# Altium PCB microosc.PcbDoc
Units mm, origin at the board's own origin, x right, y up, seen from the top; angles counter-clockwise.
Board outline 134 x 40 mm, 2 copper layers (Top Layer, Bottom Layer); 144 components, 144 nets, 580 pads, 43 vias.
Unrouted connection lines stored in the file: 8.
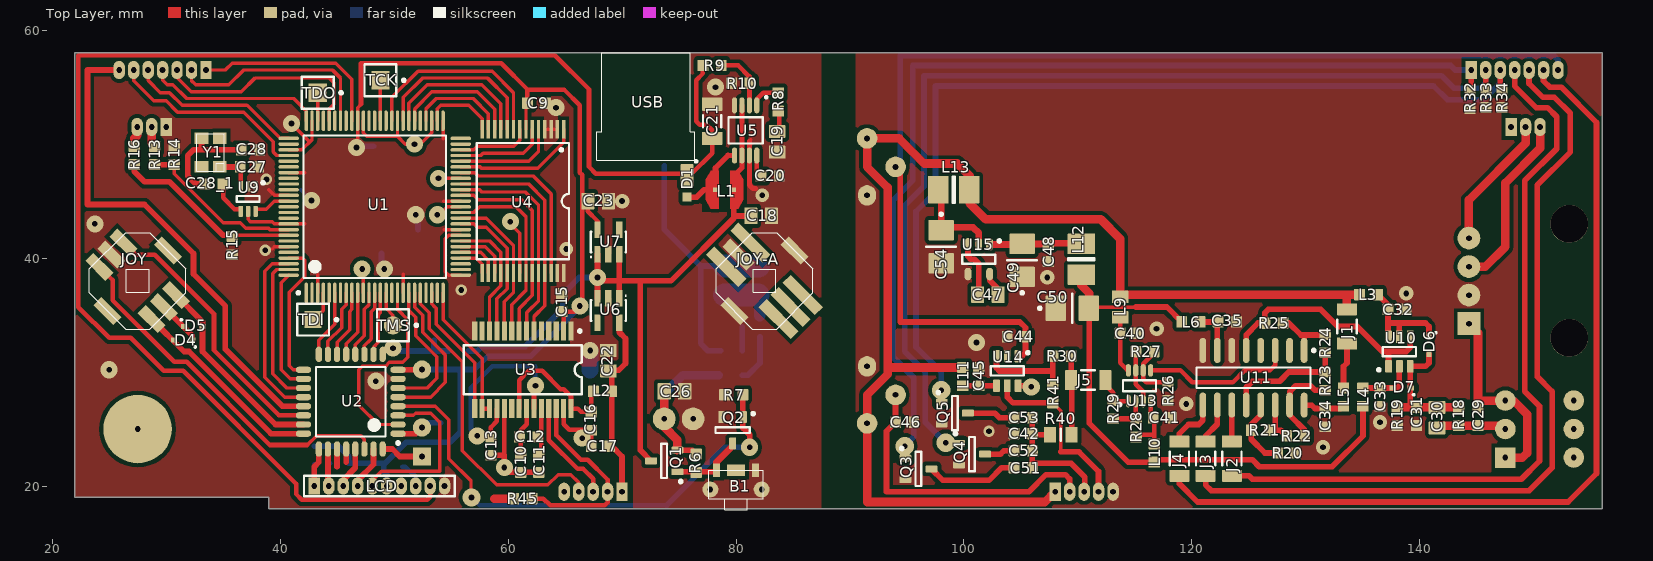
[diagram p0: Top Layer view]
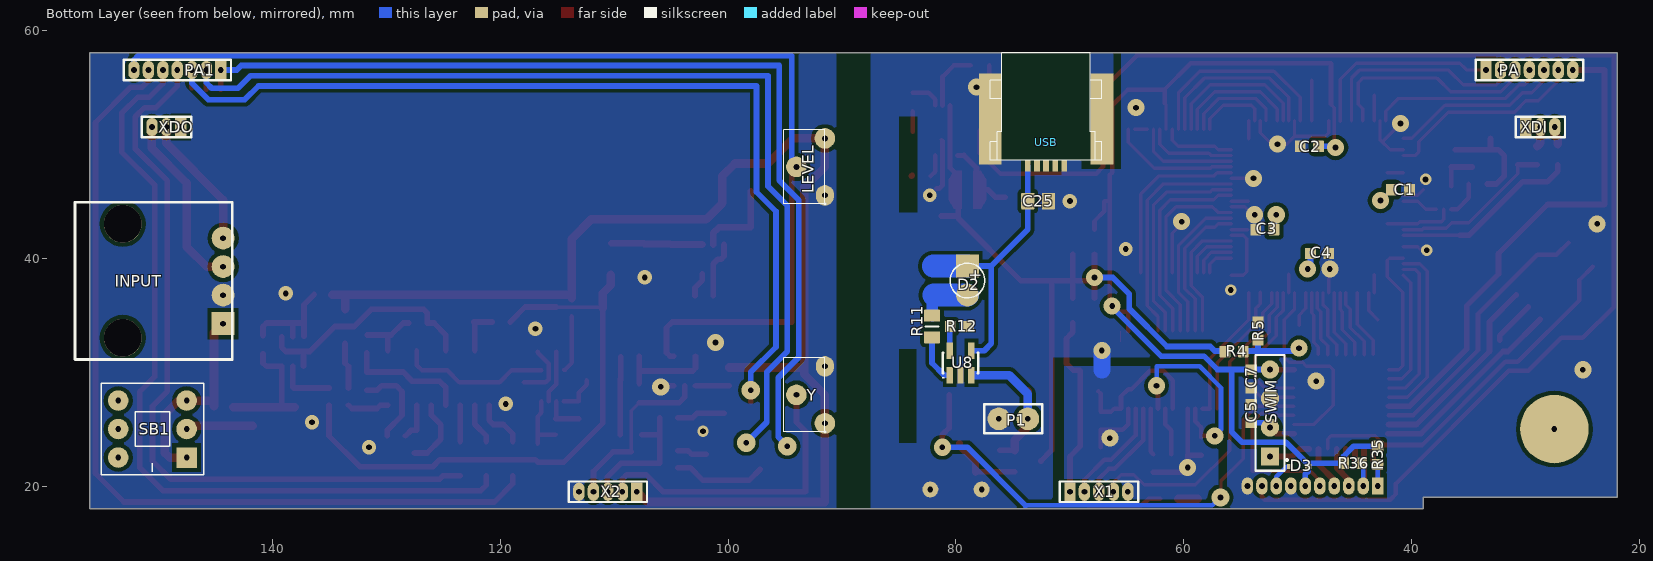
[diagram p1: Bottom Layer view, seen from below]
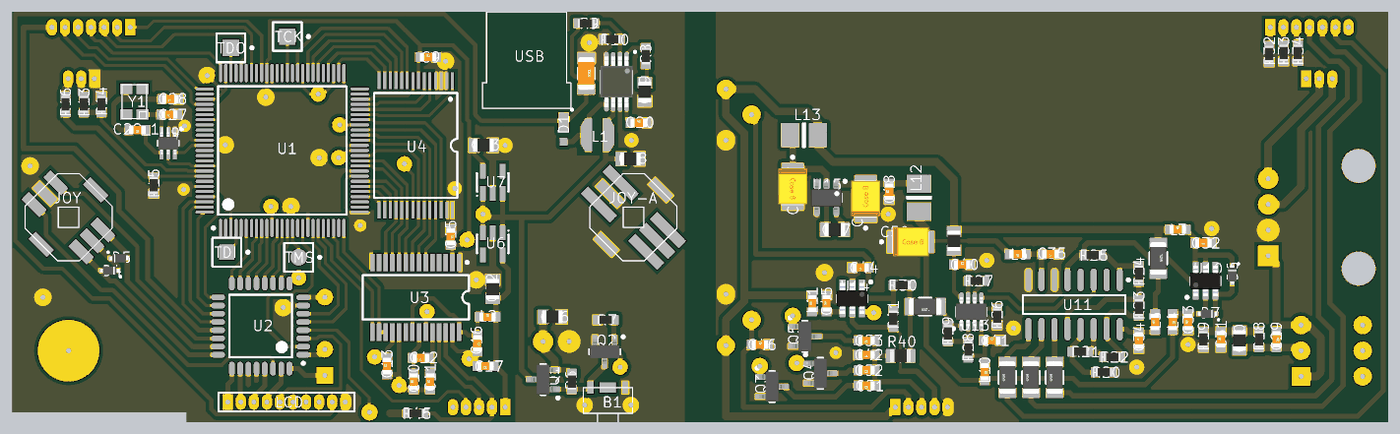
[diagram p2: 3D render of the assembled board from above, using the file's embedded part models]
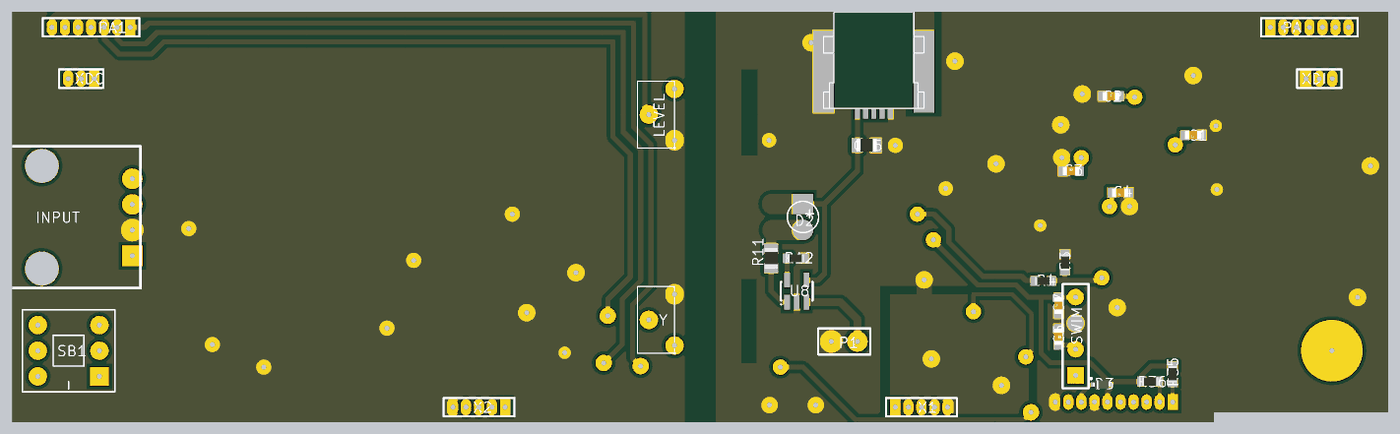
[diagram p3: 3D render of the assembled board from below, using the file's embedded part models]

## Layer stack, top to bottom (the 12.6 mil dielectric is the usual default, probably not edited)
Top Layer: signal copper 0.0356
Dielectric: dielectric 0.32, FR-4, Dk 4.8
Bottom Layer: signal copper 0.0356

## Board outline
22,19 39,19 39,18 156,18 156,58 22,58

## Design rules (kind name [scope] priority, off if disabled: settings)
Clearance Clearance_1 [IsPad Or IsTrack vs IsPad Or IsTrack] p1: gap=0.2
Clearance [All] p2: gap=0.35
ComponentClearance [All] p1 off: gap=0.254 collisioncheckmode=3 verticalgap=0.254 showdistances=FALSE
FanoutControl Fanout_BGA [IsBGA] p1 off: bgadir=Out bgaviamode=Centered fanoutstyle=Auto fanoutdirection=Alternating viagrid=0.025 // Fanout_BGA (Default Rule)
FanoutControl Fanout_LCC [IsLCC] p2 off: bgadir=Out bgaviamode=Centered fanoutstyle=Auto fanoutdirection=Alternating viagrid=0.025 // Fanout_LCC (Default Rule)
FanoutControl Fanout_SOIC [IsSOIC] p3 off: bgadir=Out bgaviamode=Centered fanoutstyle=Auto fanoutdirection=Alternating viagrid=0.025 // Fanout_SOIC (Default Rule)
FanoutControl Fanout_Small [(CompPinCount < 5)] p4 off: bgadir=Out bgaviamode=Centered fanoutstyle=Auto fanoutdirection=OutThenIn viagrid=0.025 // Fanout_Small (Default Rule)
FanoutControl Fanout_Default [All] p5 off: bgadir=Out bgaviamode=Centered fanoutstyle=Auto fanoutdirection=Alternating viagrid=0.025 // Fanout_Default (Default Rule)
HoleSize [All] p1 off: absolutevalues=TRUE maxlimit=2.54 minlimit=0.025 maxpercent=80.000 minpercent=20.000
HoleToHoleClearance [All] p1 off: gap=0.254 allowstackedmicrovias=TRUE
LayerPairs [All] p1 off: enforce=TRUE
MinimumSolderMaskSliver [All] p1 off: minsoldermaskwidth=0.254
NetAntennae [All] p1 off: netantennaetolerance=0
PlaneConnect [All] p1: planeconnectstyle=Relief reliefexpansion=0.508 reliefentries=4 reliefconductorwidth=0.5 reliefairgap=-0.1
PolygonConnect [All] p1: connectstyle=Relief reliefconductorwidth=0.5 reliefentries=4 polygonreliefangle="90 Angle" airgapwidth=-0.1
RoomDefinition analog [InComponentClass('analog')] p1: confinementstyle=ConfineOut formatcopy=TRUE lockcomponents=FALSE outline 101.6,60.5 92.6,60.5 92.6,58.5 101.6,58.5
RoomDefinition dig [InComponentClass('dig')] p2: confinementstyle=ConfineOut formatcopy=TRUE lockcomponents=FALSE outline 22.9,58.4 30.8,58.4 30.8,60.6 22.9,60.6
RoutingVias [All] p1: holewidth=0.5 width=1.6 viastyle="Through Hole" minholewidth=0.5 minwidth=1 maxholewidth=0.5 maxwidth=1.6
SilkToSilkClearance [All] p1 off: silktosilkclearance=0.254
SilkscreenOverComponentPads [IsPad] p1 off: minsilkscreentomaskgap=0.254
SolderMaskExpansion [All] p1 off: expansion=0.102
Width [All] p1 off: maxlimit=2 minlimit=0.2 preferedwidth=0.3
14 further rules are at their usual default settings.

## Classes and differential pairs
component class analog: C29 C30 C31 C32 C33 C34 C35 C40 C41 C42 C44 C45 C46 C47 C48 C49 C50 C51 C52 C53 C54 D6 D7 INPUT J1 J2 J3 J4 J5 L3 L4 L5 L6 L9 L10 L11 L12 L13 LEVEL PA1 Q3 Q4 Q5 R18 R19 R20 R21 R22 R23 R24 R25 R26 R27 R28 R29 R30 R32 R33 R34 R40 R41 SB1 U10 U11 U13 U14 U15 X2 XDO Y
component class dig: B1 C1 C2 C3 C4 C5 C7 C9 C10 C11 C12 C13 C15 C16 C17 C18 C19 C20 C21 C22 C23 C25 C26 C27 C28 C28_1 D1 D2 D3 D4 D5 JOY JOY-A L1 L2 LCD P1 PA Q1 Q2 R4 R5 R6 R7 R8 R9 R10 R11 R12 R13 R14 R15 R16 R35 R36 R45 SWIM TCK TDI TDO TMS U1 U2 U3 U4 U5 U6 U7 U8 U9 USB X1 XDI Y1

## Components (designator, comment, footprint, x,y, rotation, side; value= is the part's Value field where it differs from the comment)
B1 "Micro Button" "Micro Button" 80,21.4 r180 top
C1 "Cap" C0603NH080 41,46 r0 bottom
C2 "Cap" C0603NH080 49,49.8 r180 bottom
C3 "Cap" C0603NH080 52.9,42.5 r180 bottom
C4 "Cap" C0603NH080 48.1,40.4 r0 bottom
C5 "Cap" C0603NH080 54.1,26.35 r270 bottom
C7 "Cap" C0603NH080 54.1,29.4 r90 bottom
C9 "Cap" C0603NH080 62.5,53.6 r0 top
C10 "Cap" C0603NH080 61.1,22 r90 top
C11 "Cap" C0603NH080 62.7,22 r90 top
C12 "Cap" C0603NH080 61.8,24.3 r180 top
C13 "Cap" C0603NH080 58.5,23.5 r90 top
C15 "Cap" C0603NH080 64.7,36.1 r270 top
C16 "Cap" C0603NH080 67.3,25.7 r270 top
C17 "Cap" C0603NH080 68.1,23.5 r180 top
C18 "Cap" C0805NH145#1 82.2,43.7 r180 top
C19 "Cap" C0805NH145#1 83.6,50.2 r90 top
C20 "Cap" C0603NH080 83,47.2 r0 top
C21 "Cap" C1206NH190 77.9,52 r270 top
C22 "Cap" C0805NH145#1 68.8,31 r270 top
C23 "Cap" C0805NH145#1 67.9,45 r180 top
C25 "Cap" C0805NH145#1 72.8,45 r180 bottom
C26 "Cap" C0805NH145#1 74.6,28.3 r180 top
C27 "Cap" C0603NH080 37.3,48 r180 top
C28 "Cap" C0603NH080 37.4,49.5 r180 top
C28_1 "Cap" C0603NH080 34.2,46.5 r180 top
C29 "Cap" C0603NH080 145.1,26.1 r270 top
C30 "Cap" C0805NH145#1 141.5,26 r270 top
C31 "Cap" C0603NH080 139.7,26.1 r90 top
C32 "Cap" C0603NH080 138,35.5 r180 top
C33 "Cap" C0603NH080 136.5,27.8 r90 top
C34 "Cap" C0603NH080 131.7,26 r90 top
C35 "Cap" C0603NH080 123.1,34.4 r180 top
C40 "Cap" C0603NH080 114.5,33.4 r0 top
C41 "Cap" C0603NH080 117.4,26 r0 top
C42 "Cap" C0603NH080 105.2,24.6 r180 top
C44 "Cap" C0603NH080 104.6,33.1 r180 top
C45 "Cap" C0603NH080 101.3,29.6 r90 top
C46 "Cap" C0603NH080 94.8,25.6 r0 top
C47 "Cap" C0805NH145#1 102.1,36.8 r0 top
C48 "Cap" C0603NH080 107.4,40.5 r90 top
C49 "ECap" CAPMP3528X210N_KEMET 105.1,39.8 r90 top
C50 "ECap" CAPMP3528X210N_KEMET 109.5,35.6 r0 top
C51 "Cap" C0603NH080 105.2,21.6 r180 top
C52 "Cap" C0603NH080 105.2,23.1 r180 top
C53 "Cap" C0603NH080 105.2,26 r180 top
C54 "ECap" CAPMP3528X210N_KEMET 98,41 r270 top
D1 "D_Schottky" SOD323FL_VISHAY_MICROSMP 75.7,46.6 r270 top
D2 "Green" SvetoDiod-D3 79,39.3 r270 bottom
D3 "Diode" SOD523 49.9,21.7 r180 bottom
D4 "Diode" SOD523 31.5,32.8 r180 top
D5 "Diode" SOD523 32.4,34 r0 top
D6 "Diode" SOD523 140.8,32.4 r270 top
D7 "Diode" SOD523 138.4,28.6 r180 top
INPUT "4pin" 4pin_2.5_Audio 144.3,38 r90 bottom
J1 "R" R1206NH084 133.6,34 r270 top
J2 "R" R1206NH084 123.5,22.4 r90 top
J3 "R" R1206NH084 121.2,22.4 r90 top
J4 "R" R1206NH084 118.9,22.4 r90 top
J5 "R" R1206NH084 110.9,29.3 r180 top
JOY "Joystick" Joystick#1 27.5,38 r270 top
JOY-A "Joystick" Joystick#2 82.5,38 r270 top
L1 "L" L1212_muR_LQH3NP 79,46 r180 top
L2 "BEAD" C0603NH080 68.3,28.3 r0 top
L3 "BEAD" C0603NH080 135.5,36.8 r0 top
L4 "BEAD" C0603NH080 135,27.8 r270 top
L5 "BEAD" C0603NH080 133.3,27.8 r90 top
L6 "BEAD" C0603NH080 119.9,34.4 r180 top
L9 "BEAD" C0805NH145#2 113.7,35.7 r90 top
L10 "BEAD" C0603NH080 116.7,22.9 r270 top
L11 "BEAD" C0603NH080 99.9,29.6 r90 top
L12 "L" L1210_muR_LQH32 110.3,39.9 r270 top
L13 "L" L1210_muR_LQH32 99.1,46 r0 top
LCD "MHDR1X10" MHDR1X10 43,20 r0 top
LEVEL "Res_Var" CA6H#1 91.5,48 r90 bottom
P1 "Header 2" HDR1X2 73.7,25.9 r0 bottom
PA "MHDR1X7" MHDR1X7 33.5,56.5 r180 bottom
PA1 "MHDR1X7" MHDR1X7 144.5,56.5 r0 bottom
Q1 "IRLML2244" SOT23-3_DISCRETE 73.7,22.2 r180 top
Q2 "IRLML2402" SOT23-3_DISCRETE 79.7,24.9 r270 top
Q3 "IRLML2402" SOT23-3_DISCRETE 96,21.5 r0 top
Q4 "IRLML2402" SOT23-3_DISCRETE 100.7,22.8 r0 top
Q5 "IRLML2402" SOT23-3_DISCRETE 99.2,26.4 r0 top
R4 "R" R0603N 55.6,31.8 r0 bottom
R5 "R" R0603N 53.5,33.6 r270 bottom
R6 "R" R0603N 76.5,22 r270 top
R7 "R" R0603N 79.8,28 r0 top
R8 "R" R0603N 83.7,53.7 r90 top
R9 "R" R0603N 77.9,56.9 r180 top
R10 "R" R0603N 80.4,55.35 r0 top
R11 "R" R0805NH070 82.1,34 r270 bottom
R12 "R" R0603N 79.7,34 r0 bottom
R13 "R" R0603N 29,49 r90 top
R14 "R" R0603N 30.7,49 r90 top
R15 "R" R0603N 35.8,41.1 r270 top
R16 "R" R0603N 27.2,49 r90 top
R18 "R" R0603N 143.4,26.1 r270 top
R19 "R" R0603N 138,26.1 r90 top
R20 "R" R0603N 128.3,22.9 r180 top
R21 "R" R0603N 126,24.9 r0 top
R22 "R" R0603N 129.1,24.4 r0 top
R23 "R" R0603N 131.7,29.2 r90 top
R24 "R" R0603N 131.7,32.5 r90 top
R25 "R" R0603N 127.2,34.3 r180 top
R26 "R" R0603N 117.9,28.3 r270 top
R27 "R" R0603N 115.9,31.8 r180 top
R28 "R" R0603N 115.1,25.1 r270 top
R29 "R" R0603N 113.1,26.7 r90 top
R30 "R" R0603N 108.6,31.4 r180 top
R32 "R" R0603N 144.4,53.9 r270 top
R33 "R" R0603N 145.8,54 r270 top
R34 "R" R0603N 147.2,54 r270 top
R35 "R" R0603N 43,22.7 r90 bottom
R36 "R" R0603N 45.2,22 r0 bottom
R40 "R" R0805NH070 108.5,24.5 r180 top
R41 "R" R0603N 107.8,28.1 r270 top
R45 "R" R0603N 61.3,18.9 r180 top
SB1 "SB_8x8" SB_8x8 150.5,25 r90 bottom
SWIM "Header 4" HDR1X4 52.45,22.6 r90 bottom
TCK "Socket" PIN1#1 48.8,55.6 r270 top
TDI "Socket" PIN1#2 42.9,34.6 r270 top
TDO "Socket" PIN1#1 43.3,54.5 r270 top
TMS "Socket" PIN1#3 49.9,34.1 r270 top
U1 "EPM3064ATC-100" TQFP100_N 48.3,44.5 r90 top
U2 "STM8L151K6T" TQFP32_L 46.2,27.4 r180 top
U3 "AD9203" RS-28 61.3,30.2 r180 top
U4 "AS7C3256A" TSOP28 61.3,45 r180 top
U5 "ADP1612" MSOP8 80.85,51.2 r270 top
U6 "ADP150AU-3.0" RT-5 68.8,35.4 r180 top
U7 "ADP150AU-3.0" RT-5 68.8,41.4 r0 top
U8 "MCP73831T" S5 79.6,30.8 r180 bottom
U9 "74AUP1Z04" SC70-6 37.2,45.2 r270 top
U10 "OPA357AIDBV" SOT23-6RR 138.2,31.8 r90 top
U11 "MC74HC4051AD" 751B-05_N 125.4,29.5 r270 top
U13 "AD8039" TSOT23-8 115.4,28.8 r90 top
U14 "TLV3501AIDBV" SOT23-6RR 103.8,30.1 r270 top
U15 "LM828" SOT23-5 101.3,39.9 r270 top
USB "USB-miniB" USB-B_CrossBoard 72.1,48.1 r0 top locked
X1 "MHDR1X5" MHDR1X5 70,19.5 r180 bottom
X2 "MHDR1X5" MHDR1X5 108,19.5 r0 bottom
XDI "MHDR1X3" MHDR1X3 30,51.5 r180 bottom
XDO "MHDR1X3" MHDR1X3 148,51.5 r0 bottom
Y "Res_Var" CA6H#2 91.5,28 r90 bottom
Y1 "Quarz Rezonator SMD" QUARZ_REC_25x32 34.7,48 r90 top

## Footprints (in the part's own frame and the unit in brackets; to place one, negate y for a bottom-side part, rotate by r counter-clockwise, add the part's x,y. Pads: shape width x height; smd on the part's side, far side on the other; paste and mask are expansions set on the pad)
4pin_2.5_Audio [mm] "Internal Audio connector for cabel"
  rect 2x2 hole 0.5: 1(-3.75,0)
  round 2 hole 0.5: 2(-1.25,0) 3(1.25,0) 4(3.75,0)
  round 3.3 hole 3.3: 5(-5,8.8) 5(5,8.8)
  silkscreen extent -6.9,-0.8 6.9,13
751B-05_N [mm] "SOIC, 16-Leads, Body 9.9x3.9mm, Pitch 1.27mm, IPC Medium Density"
  oval 2.2x0.6 smd: 1(-2.4,4.445) 2(-2.4,3.175) 3(-2.4,1.905) 4(-2.4,0.635) 5(-2.4,-0.635) 6(-2.4,-1.905) 7(-2.4,-3.175) 8(-2.4,-4.445) 9(2.4,-4.445) 10(2.4,-3.175) 11(2.4,-1.905) 12(2.4,-0.635) 13(2.4,0.635) 14(2.4,1.905) 15(2.4,3.175) 16(2.4,4.445)
  silkscreen extent -2.52,-5 0.9,5.42, body extent -1.95,-4.95 1.95,4.95, height 1.75
C0603NH080 [mm] "Capacitor,Chip;1.60mm L X 0.80mm W X 0.90mm H"
  rrect10% 0.95x1 smd paste-0.025 mask+0.05: 1(-0.8,0) 2(0.8,0)
  body extent -0.8,-0.4 0.8,0.4, height 0.3
C0805NH145#1 [mm] "Capacitor,Chip;2.00mm L X 1.25mm W X 1.45mm H"
  rrect10% 1.15x1.45 smd paste-0.025 mask+0.05: 1(-0.9,0) 2(0.9,0)
  body extent -1,-0.62 1,0.63, height 0.6
C0805NH145#2 [mm] "Capacitor,Chip;2.00mm L X 1.25mm W X 1.45mm H"
  rrect10% 1.1x1.45 smd paste-0.025 mask+0.05: 1(-0.9,0) 2(0.9,0)
  body extent -1,-0.62 1,0.63, height 0.6
C1206NH190 [mm] "Capacitor, Chip; 3.20mm L X 1.60mm W X 1.90mm H"
  rrect10% 1.15x1.8 smd paste-0.025 mask+0.05: 1(-1.5,0) 2(1.5,0)
  silkscreen extent -0.55,-0.8 0.55,0.8, body extent -1.6,-0.8 1.6,0.8, height 1
CA6H#1 [mm] "Variable Resistor 6.5x6.5x3.5mm Vertical"
  oval 1.8x1.6 hole 0.5: 1(-2.5,0)
  round 1.8 hole 0.5: 2(2.5,0) 3(0,2.5)
  silkscreen extent -3.25,0 3.25,3.6
CA6H#2 [mm] "Variable Resistor 6.5x6.5x3.5mm Vertical"
  round 1.8 hole 0.5: 1(-2.5,0) 3(0,2.5)
  oval 1.8x1.6 hole 0.5: 2(2.5,0)
  silkscreen extent -3.25,0 3.25,3.6
CAPMP3528X210N_KEMET [mm]
  rrect11% 1.8x2.25 smd paste-0.05 mask+0.05: A(-1.45,0) C(1.45,0)
  silkscreen extent -2.97,-1.3 0,1.3, body extent -1.85,-1.41 1.85,1.41, height 2.09
HDR1X2 [mm] "Connector; Header; 2 Position"
  round 2 hole 0.5: 1(0,0) 2(2.54,0)
  silkscreen extent -1.27,-1.27 3.81,1.27
HDR1X4 [mm] "Connector; Header; 4 Position"
  rect 1.6x1.6 hole 0.5: 1(0,0)
  round 1.6 hole 0.5: 2(2.54,0) 4(7.62,0)
  round 1.6 smd: 3(5.08,0)
  silkscreen extent -1.27,-1.27 8.89,1.27
Joystick#1 [mm] "Joystick Siemens"
  rect 2.5x1 smd rot 45: 1(-3.359,-1.237) 2(-2.298,-2.298) 3(-1.237,-3.359) 4(3.359,1.237) 5(2.298,2.298) 6(1.237,3.359) 7(-2.652,2.652) 8(2.652,-2.652)
  silkscreen extent -4.24,-4.24 4.24,4.24
Joystick#2 [mm] "Joystick Siemens"
  rect 4x1 smd rot 45: 1(-3.359,-1.237) 3(-1.237,-3.359) 4(3.359,1.237) 5(2.298,2.298) 6(1.237,3.359)
  rect 3x1 smd rot 45: 2(-2.298,-2.298)
  rect 2.5x1 smd rot 45: 7(-2.652,2.652) 8(2.652,-2.652)
  silkscreen extent -4.24,-4.24 4.24,4.24
L1210_muR_LQH32 [mm]
  rrect5% 1.8x2.4 smd paste-0.025 mask+0.05: 1(-1.35,0) 2(1.35,0)
  silkscreen extent -0.1,-1.15 0.1,1.15
L1212_muR_LQH3NP [mm]
  rect 0.4x0.4 smd paste-0.4 mask-0.4: 1(-0.8,0) 2(0.8,0)
  Top Layer region: 0.5,1.65 1.2,1.65 1.65,0.9 1.65,-0.9 1.343,-1.411 1.2,-1.65 0.5,-1.65
  Top Layer region: -0.5,1.65 -1.2,1.65 -1.65,0.9 -1.65,-0.9 -1.341,-1.415 -1.2,-1.65 -0.5,-1.65
  body extent -1.49,-1.5 1.5,1.5, height 1.5
MHDR1X3 [mm] "Connector; Header; 3 Position"
  rect 1x1.6 hole 0.5: 1(0,0)
  oval 1x1.6 hole 0.5: 2(1.27,0) 3(2.54,0)
  silkscreen extent -0.9,-0.9 3.44,0.9
MHDR1X5 [mm] "Connector; Header; 5 Position"
  rect 1x1.6 hole 0.5: 1(0,0)
  oval 1x1.6 hole 0.5: 2(1.27,0) 3(2.54,0) 4(3.81,0) 5(5.08,0)
  silkscreen extent -0.9,-0.9 5.98,0.9
MHDR1X7 [mm] "Connector; Header; 7 Position"
  rect 1x1.6 hole 0.5: 1(0,0)
  oval 1x1.6 hole 0.5: 2(1.27,0) 3(2.54,0) 4(3.81,0) 5(5.08,0) 6(6.35,0) 7(7.62,0)
  silkscreen extent -0.9,-0.9 8.52,0.9
MHDR1X10 [mm] "Connector; Header; 10 Position"
  rect 1x1.5 hole 0.5: 1(0,0)
  oval 1x1.5 hole 0.5: 2(1.27,0) 3(2.54,0) 4(3.81,0) 5(5.08,0) 6(6.35,0) 7(7.62,0) 8(8.89,0) 9(10.16,0) 10(11.43,0)
  silkscreen extent -0.9,-0.9 12.33,0.9
"Micro Button" [mm]
  rect 0.6x1.2 smd: 1(-1.7,0) 2(1.7,0)
  round 1.4 hole 0.5: 3(-2.25,1.7) 3(2.25,1.7)
  rect 1.6x1 smd: 4(0,0)
  silkscreen extent -2.4,0 2.4,3.5
MSOP8 [mm] "SOP,0.65mm pitch;8 pin,3.00mm W X 3.00mm L X 1.09mm H body"
  oval 1.4x0.45 smd mask+0.05: 1(-2.2,0.975) 2(-2.2,0.325) 3(-2.2,-0.325) 4(-2.2,-0.975) 5(2.2,-0.975) 6(2.2,-0.325) 7(2.2,0.325) 8(2.2,0.975)
  silkscreen extent -3,-1.5 1.15,1.9, body extent -2.47,-1.55 2.47,1.55, height 1.1
PIN1#1 [mm] "Connector; Plug"
  rect 1.6x1.6 smd: 1(0,0)
  silkscreen extent -1.4,-1.4 1.4,2.18
PIN1#2 [mm] "Connector; Plug"
  rect 1.5x1.5 smd: 1(0,0)
  silkscreen extent -1.4,-1.4 1.4,2.18
PIN1#3 [mm] "Connector; Plug"
  round 1.6 smd: 1(0,0)
  silkscreen extent -1.4,-1.4 1.4,2.18
QUARZ_REC_25x32 [mm] "Quarz rezonatro or generator 2.5x3.2mm"
  rect 1x1.2 smd: 1(0,0) 2(2.5,0) 3(2.5,1.6) 4(0,1.6)
  silkscreen extent -0.4,-0.4 2.9,2
R0603N [mm] "Resistor, Chip, 1.60mm L x 0.80mm W x 0.50mm H"
  rrect10% 0.95x1 smd paste-0.025 mask+0.05: 1(-0.8,0) 2(0.8,0)
  body extent -0.8,-0.4 0.8,0.4, height 0.46
R0805NH070 [mm] "Resistor, Chip, 2.00mm L x 1.25mm W x 0.70mm H"
  rrect10% 1.05x1.4 smd paste-0.025 mask+0.05: 1(-0.95,0) 2(0.95,0)
  silkscreen extent 0,-0.55 0,0.55, body extent -1,-0.62 1,0.63, height 0.41
R1206NH084 [mm] "Resistor, Chip, 3.20mm L x 1.60mm W x 0.84mm H"
  rrect10% 1.05x1.75 smd paste-0.025 mask+0.05: 1(-1.5,0) 2(1.5,0)
  silkscreen extent -0.6,-0.85 0.6,0.85, body extent -1.6,-0.8 1.6,0.8, height 1
RS-28 [mm] "SSOP; 28 Leads; Body Width 5.3 mm; Pitch 0.65 mm"
  rect 0.45x1.7 smd: 1(-4.225,-3.4) 2(-3.575,-3.4) 3(-2.925,-3.4) 4(-2.275,-3.4) 5(-1.625,-3.4) 6(-0.975,-3.4) 7(-0.325,-3.4) 8(0.325,-3.4) 9(0.975,-3.4) 10(1.625,-3.4) 11(2.275,-3.4) 12(2.925,-3.4) 13(3.575,-3.4) 14(4.225,-3.4) 15(4.225,3.4) 16(3.575,3.4) 17(2.925,3.4) 18(2.275,3.4) 19(1.625,3.4) 20(0.975,3.4) 21(0.325,3.4) 22(-0.325,3.4) 23(-0.975,3.4) 24(-1.625,3.4) 25(-2.275,3.4) 26(-2.925,3.4) 27(-3.575,3.4) 28(-4.225,3.4)
  silkscreen extent -5.18,-3.52 5.18,2.15
RT-5 [mm] "SOT-23/SC-74A; 5 Leads; Body 3.1 x 3 mm, inc. leads (LxW max)"
  rect 0.55x1.45 smd: 1(-0.95,-1.075) 2(0,-1.075) 3(0.95,-1.075) 4(0.95,1.075) 5(-0.95,1.075)
  silkscreen extent -1.58,-1.35 1.55,0.9
S5 [mm] "SOT-23/SC-74A; 5 Leads; Body 3.1 x 3 mm, inc. leads (LxW max)"
  rect 0.55x1.45 smd: 1(-0.95,-1.075) 2(0,-1.075) 3(0.95,-1.075) 4(0.95,1.075) 5(-0.95,1.075)
  silkscreen extent -1.58,-1.35 1.55,0.9
SB_8x8 [mm] "Кнопка 8х8мм"
  rect 1.8x1.8 hole 0.5: 1(-2.5,-3)
  round 1.8 hole 0.5: 2(0,-3) 3(2.5,-3) 4(2.5,3) 5(0,3) 6(-2.5,3)
  silkscreen extent -4,-4.5 4,4.5
SC70-6 [mm] "SOT,0.65mm pitch;6 pin,1.35mm W X 2.20mm L X 1.00mm H body"
  rrect40% 0.95x0.4 smd mask+0.05: 1(-1.1,0.65) 2(-1.1,0) 3(-1.1,-0.65) 4(1.1,-0.65) 5(1.1,0) 6(1.1,0.65)
  silkscreen extent -1.53,-1 0.25,1.43, body extent -1.05,-1 1.05,1, height 0.95
SOD323FL_VISHAY_MICROSMP [mm]
  rrect12% 0.8x0.8 smd paste-0.025 mask+0.05: A(1.25,0)
  rrect9% 2x1.1 smd paste-0.05 mask+0.05: C(-0.65,0)
  silkscreen extent -1.98,0.7 -1.78,0.9, body extent -1.15,-0.7 1.15,0.7, height 0.65
SOD523 [mm]
  rrect15% 0.55x0.45 smd paste-0.025 mask+0.05: A(0.8,0) C(-0.8,0)
  silkscreen extent -1.09,0.55 -1.01,0.63, body extent -0.91,-0.42 0.92,0.42, height 0.71
SOT23-3_DISCRETE [mm] "SOT,0.95mm pitch;3 pin,1.40mm W X 3.04mm L X 1.12mm H body"
  rrect25% 1.05x0.6 smd paste-0.025 mask+0.05: 1(-1.15,0.95) 2(-1.15,-0.95) 3(1.15,0)
  silkscreen extent -1.58,-1.5 0.25,1.92, body extent -1.25,-1.46 1.23,1.46, height 1.02
SOT23-5 [mm] "SOT,0.95mm pitch;5 pin,1.70mm W X 3.00mm L X 1.45mm H body"
  oval 1.1x0.6 smd mask+0.05: 1(-1.3,0.95) 2(-1.3,0) 3(-1.3,-0.95) 4(1.3,-0.95) 5(1.3,0.95)
  silkscreen extent -1.72,-1.45 0.4,1.92, body extent -1.5,-1.52 1.5,1.48, height 1.55
SOT23-6RR [mm] "SOT,0.95mm pitch;6 pin,1.70mm W X 3.00mm L X 1.45mm H body"
  rrect25% 1.1x0.6 smd mask+0.05: 1(-1.3,0.95) 2(-1.3,0) 3(-1.3,-0.95) 4(1.3,-0.95) 5(1.3,0) 6(1.3,0.95)
  silkscreen extent -1.72,-1.45 0.4,1.92, body extent -1.5,-1.5 1.5,1.5, height 1.3
SvetoDiod-D3 [mm] "SvetoDiod Diametr=3mm"
  rect 2x2 smd: A(0,0)
  round 2 smd: K(2.54,0)
  silkscreen extent -0.25,-1.52 2.79,1.52
TQFP32_L [mm] "Thin QFP, 32-Leads, Body 7x7mm, Pitch 0.8mm, IPC High Density"
  oval 1.35x0.55 smd: 1(-4.15,2.8) 2(-4.15,2) 3(-4.15,1.2) 4(-4.15,0.4) 5(-4.15,-0.4) 6(-4.15,-1.2) 7(-4.15,-2) 8(-4.15,-2.8) 17(4.15,-2.8) 18(4.15,-2) 19(4.15,-1.2) 20(4.15,-0.4) 21(4.15,0.4) 22(4.15,1.2) 23(4.15,2) 24(4.15,2.8)
  oval 0.55x1.35 smd: 9(-2.8,-4.15) 10(-2,-4.15) 11(-1.2,-4.15) 12(-0.4,-4.15) 13(0.4,-4.15) 14(1.2,-4.15) 15(2,-4.15) 16(2.8,-4.15) 25(2.8,4.15) 26(2,4.15) 27(1.2,4.15) 28(0.4,4.15) 29(-0.4,4.15) 30(-1.2,4.15) 31(-2,4.15) 32(-2.8,4.15)
  silkscreen extent -4.28,-3.05 3.05,3.75, body extent -3.5,-3.5 3.5,3.5, height 1.6
TQFP100_N [mm] "Thin QFP, 100-Leads, Body 14x14mm, Pitch 0.5mm, IPC Medium Density"
  oval 1.8x0.3 smd: 1(-7.55,6) 2(-7.55,5.5) 3(-7.55,5) 4(-7.55,4.5) 5(-7.55,4) 6(-7.55,3.5) 7(-7.55,3) 8(-7.55,2.5) 9(-7.55,2) 10(-7.55,1.5) 11(-7.55,1) 12(-7.55,0.5) 13(-7.55,0) 14(-7.55,-0.5) 15(-7.55,-1) 16(-7.55,-1.5) 17(-7.55,-2) 18(-7.55,-2.5) 19(-7.55,-3) 20(-7.55,-3.5) 21(-7.55,-4) 22(-7.55,-4.5) 23(-7.55,-5) 24(-7.55,-5.5) 25(-7.55,-6) 51(7.55,-6) 52(7.55,-5.5) 53(7.55,-5) 54(7.55,-4.5) 55(7.55,-4) 56(7.55,-3.5) 57(7.55,-3) 58(7.55,-2.5) 59(7.55,-2) 60(7.55,-1.5) 61(7.55,-1) 62(7.55,-0.5) 63(7.55,0) 64(7.55,0.5) 65(7.55,1) 66(7.55,1.5) 67(7.55,2) 68(7.55,2.5) 69(7.55,3) 70(7.55,3.5) 71(7.55,4) 72(7.55,4.5) 73(7.55,5) 74(7.55,5.5) 75(7.55,6)
  oval 0.3x1.8 smd: 26(-6,-7.55) 27(-5.5,-7.55) 28(-5,-7.55) 29(-4.5,-7.55) 30(-4,-7.55) 31(-3.5,-7.55) 32(-3,-7.55) 33(-2.5,-7.55) 34(-2,-7.55) 35(-1.5,-7.55) 36(-1,-7.55) 37(-0.5,-7.55) 38(0,-7.55) 39(0.5,-7.55) 40(1,-7.55) 41(1.5,-7.55) 42(2,-7.55) 43(2.5,-7.55) 44(3,-7.55) 45(3.5,-7.55) 46(4,-7.55) 47(4.5,-7.55) 48(5,-7.55) 49(5.5,-7.55) 50(6,-7.55) 76(6,7.55) 77(5.5,7.55) 78(5,7.55) 79(4.5,7.55) 80(4,7.55) 81(3.5,7.55) 82(3,7.55) 83(2.5,7.55) 84(2,7.55) 85(1.5,7.55) 86(1,7.55) 87(0.5,7.55) 88(0,7.55) 89(-0.5,7.55) 90(-1,7.55) 91(-1.5,7.55) 92(-2,7.55) 93(-2.5,7.55) 94(-3,7.55) 95(-3.5,7.55) 96(-4,7.55) 97(-4.5,7.55) 98(-5,7.55) 99(-5.5,7.55) 100(-6,7.55)
  silkscreen extent -7.67,-6.25 6.25,6.82, body extent -7,-7 7,7, height 1.2
TSOP28 [mm] "Shrink Small Outline, Plastic, Thin; 28 Leads; Body Width 11.8 mm; Pitch 0.55 mm"
  rect 0.3x1.6 smd: 1(-3.575,-6.3) 2(-3.025,-6.3) 3(-2.475,-6.3) 4(-1.925,-6.3) 5(-1.375,-6.3) 6(-0.825,-6.3) 7(-0.275,-6.3) 8(0.275,-6.3) 9(0.825,-6.3) 10(1.375,-6.3) 11(1.925,-6.3) 12(2.475,-6.3) 13(3.025,-6.3) 14(3.575,-6.3) 15(3.575,6.3) 16(3.025,6.3) 17(2.475,6.3) 18(1.925,6.3) 19(1.375,6.3) 20(0.825,6.3) 21(0.275,6.3) 22(-0.275,6.3) 23(-0.825,6.3) 24(-1.375,6.3) 25(-1.925,6.3) 26(-2.475,6.3) 27(-3.025,6.3) 28(-3.575,6.3)
  silkscreen extent -4.05,-5.1 4.05,5.1
TSOT23-8 [mm] "SOT,0.65mm pitch;8 pin,1.75mm W X 3.00mm L X 1.00mm H body"
  oval 1.1x0.45 smd mask+0.05: 1(-1.35,0.975) 2(-1.35,0.325) 3(-1.35,-0.325) 4(-1.35,-0.975) 5(1.35,-0.975) 6(1.35,-0.325) 7(1.35,0.325) 8(1.35,0.975)
  silkscreen extent -1.77,-1.45 0.48,1.87, body extent -1.4,-1.5 1.4,1.5, height 1.11
USB-B_CrossBoard [mm]
  rect 0.5x1 smd far side: 1(1.6,0) 2(0.8,0) 3(0,0) 4(-0.8,0) 5(-1.6,0)
  rect 2x8 smd far side: 6(-4.9,4.1) 6(4.9,4.1)
  silkscreen extent -4.3,0.5 4.3,9.9

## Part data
C1 C2 C3 C4 C5 C7 C9 C10 C11 C12 C13 C15 C16 C17 C20 C29 C32 C33 C34 C35 C40 C41 C44 C45 C46: library part CL10B104KB8NNNC
C18 C47: library part GRM21BR61A106KE19L
C19: library part CL21C222JBFNNNE
C21: library part GRM31CR61E106KA12L
C22 C23 C25 C26: library part GRM21BR71H105KA12L
C27 C28 C28_1: library part CL10C220JB8NNNC
C30: library part CL21C220JBANNNC
C31: library part CL10C470JB8NNNC
C42 C51 C52 C53: library part C0603C151J5GAC7867
C48: library part GRM188R61C225KE15D
C49 C50 C54: library part T520B476M006ATE040, "T520 Series Polymer Tantalum 40mOhm"
D1: library part MSS1P3L-M3/89A, "30V, 1A, eSMP, Surface Mount Schottky Barrier Rectifiers"
D2: library part Svetodiod, "Lite Diode"
D3 D4 D5 D7: library part BAS516,115, "High-speed switching diodes"
D6: "High-speed switching diodes"
J1 J2 J3 J4 J5: library part 12064SF1000T50
L1: library part LQH3NPN470MM0L, "Shielded Power Inductor Wire Wound"
L2: library part BLM18KG601SN1D, "High performance type for power lines up to 600ohm."
L3 L4 L5 L6 L10 L11: library part BLM18PG181SN1D, "Bead 0603 size for power lines"
L9: library part BLM21PG331SN1D, "Bead 0805 size for power lines"
L12 L13: library part LQH32CN220K23L, "Power Inductor Wire Wound"
LCD: "Header, 10-Pin"
LEVEL Y: "Variable resistor"
P1: "Header, 2-Pin"
PA PA1: "Header, 7-Pin"
Q1: library part IRLML2244TRPBF, "20V, 4.3A Single P-Channel HEXFET Power MOSFET"
Q2 Q3 Q4 Q5: library part IRLML2402TRPBF, "20V, 0.25 Ohm, Single N-Channel HEXFET Power MOSFET"
R4 R5: library part 0603SAF2002T50
R6: library part ERJ3EKF8453V
R7 R10 R29 R30 R32 R33 R34 R41: library part 0603SAF1501T50
R8: library part 0603SAF2202T50
R9: library part 0603SAF1003T50
R11: library part 0805S8F2701T50
R12: library part 0603SAF8201T50
R13 R16: library part 0603SAF2001T50
R14 R15 R35 R36 R45: library part 0603SAF1002T50
R18 R19: library part 0603SAF3003T50
R20: library part 0603SAF1000T50
R21 R26 R27 R28: library part 0603SAF2701T50
R22 R23: library part 0603SAF5102T50
R24: library part TC0350F4023T5E, "TC03 (0603) 1/16W 1% 402K 50PPM T/R-5000"
R25: library part 0603SAF5103T50
R40: library part RR1220Q-100-D
SWIM: "Header, 4-Pin"
U2: library part STM8L151Kn
U5: library part ADP1612ARMZ-R7, "20 V, 650 kHz/1.3 MHz Step-Up PWM DCDC Switching Converter"
U6 U7: library part ADP150AU, "LDO"
U8: "Li-Ion battery charger"
U9: library part 74AUP1Z04GW,125, "Low-power X-tal driver with enable and internal resistor"
U10: library part OPA357AIDBVR, "250MHz, RRIO, CMOS Operational Amplifier with Shutdown"
U11: "Analog Multiplexer/Demultiplexer"
U13: library part AD8039ARTZ-REEL7, "Dual, Low Power 350MHz, Voltage Feedback Amplifiers"
U14: library part TLV3501AIDBVR, "4.5ns Rail-to-Rail, High-Speed Comparator"
U15: library part LM828M5, "Switched Capacitor Voltage Converter"
USB: library part USB
X1 X2: "Header, 5-Pin"
XDI XDO: "Header, 3-Pin"

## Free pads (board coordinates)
  round 6 hole 0.5: 0(27.5,25)

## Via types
v1: diameter 1.5, hole 0.5, Top Layer to Bottom Layer, 26 vias
v2: diameter 1.27, hole 0.5, Top Layer to Bottom Layer, 7 vias
v3: diameter 1.6, hole 0.5, Top Layer to Bottom Layer, 4 vias
v4: diameter 1, hole 0.5, Top Layer to Bottom Layer, 4 vias
v5: diameter 1.2, hole 0.5, Top Layer to Bottom Layer, 2 vias

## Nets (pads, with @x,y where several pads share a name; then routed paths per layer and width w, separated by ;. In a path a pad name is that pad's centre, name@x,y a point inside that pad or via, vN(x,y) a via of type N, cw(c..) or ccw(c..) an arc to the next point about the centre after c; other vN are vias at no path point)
+3V: C1.2 C2.2 C3.2 C4.2 C7.2 C9.1 C15.2 C23.2 D3.A LCD.6 R35.2 R36.2 SWIM.4 U1.3 U1.18 U1.34 U1.39 U1.51 U1.66 U1.82 U1.91 U2.8 U3.2 U4.7 U7.5 U9.5 | length 116.5
  Top Layer w0.3: U9.5@37.2,44.3 37.2,43.4 37.4,43.2 39.3,43.2 39.5,43 U1.91 42.15,43 ; U1.82 42.15,47.5 ; U1.3 43.3,38.55 ; 46.8,50.45 U1.66 46.8,53.2 47.1,53.5 ; U1.18 50.8,38.6 ; 54.3,50.45 U1.51 ; 54.35,45 U1.39 ; 54.4,42.5 U1.34 ; U4.7 61.575,53.475 C9.1
  Top Layer w0.4: 47.1,53.5 47.1,57.1 59.4,57.1 61.75,54.75 ; C9.1 61.7,54.7 61.75,54.75 ; U3.2 C15.2@64.875,35.275 ; C15.2@64.9,35.3 65.8,35.3 v1(66.3,35.8) 66.5,36 66.5,47.3 66.3,47.5 66.3,53.4 64.95,54.75 61.75,54.75 ; C23.2@66.5,45 C23.2 67,44.1 67.85,43.25 U7.5
  Top Layer w0.5: U2.8 SWIM.4@52.45,30.2
  Bottom Layer w0.3: C1.2 v1(42.75,45.05)
  Bottom Layer w0.5: R35.2 45.1,23.5 46,22.6 R36.2 49.1,22 ; v1@46.8,49.8 C2.2 ; v1@48.9,39.15 C4.2 ; D3.A 49.1,21.3 49.35,21.05 LCD.6 ; 49.2,22 51.05,23.85 54.9,23.85 55.8,24.75 55.8,30.22 ; v1(51.9,43.8) 52.1,43.6 C3.2 ; SWIM.4 55.8,30.22 ; v1(66.3,35.8) 66.3,35.7 62,31.4 58.25,31.4 57.07,30.22 55.8,30.22
  other v1: 49.15,39.05 46.7,49.7
+3VA: C17.1 C22.2 J1.1 L2.2 L3.1 L9.2 L11.2 L13.2 LEVEL.2 U6.5 X1.1 X2.1 Y.1 | length 127.8
  Top Layer w0.5: U6.5 69.75,33.5 70.3,32.95 70.3,30.75 69.7,30.15 69.15,30.15 69.1,30.1 L2.2 69.1,23.5 70,22.6 X1.1
  Top Layer w0.75: 93.4,30.4 L11.2 ; X2.1 107.1,18.6 91.5,18.6 Y.1 91.5,28 93.3,29.8 93.3,46.2 91.5,48 LEVEL.2 94.3,50.5 96.5,48.3 99.4,48.3 100.5,47.2 100.5,44.8 101.9,43.4 112,43.4 113.7,41.7 L9.2@113.7,36.8 ; L9.2@113.7,36.5 L9.2@113.7,36.8 ; J1.1 133.6,36.8 ; L3.1 133.6,36.8 ; L9.2@113.7,36.8 133.6,36.8
-3VA: C50.C L4.2 L6.2 L10.2 L12.2 | length 51.4
  Top Layer w0.3: C50.C@111.1,35.7 115.1,35.7
  Top Layer w0.5: C50.C@111,35.6 111,25.5 114.4,22.1 L10.2 116.9,22.3 125.3,22.3 125.9,21.7 132.3,21.7 135,24.4 L4.2@135,27.1 ; 115.1,35.7 117.8,35.7 L6.2
  Top Layer w0.75: L12.2 110.3,37.6 111,36.9 C50.C@111,35.6
A0: U1.31 U4.17 | length 4.8
  Top Layer w0.3: U1.31 58,41 58.825,40.175 U4.17
A1: U1.30 U4.16 | length 3.8
  Top Layer w0.3: U1.30 57.6,40.5 58.275,39.825 U4.16
A2: U1.29 U4.15 | length 2.9
  Top Layer w0.3: U1.29 57.2,40 57.725,39.475 U4.15
A3: U1.52 U4.14 | length 6.5
  Top Layer w0.3: U1.52 53.8,53.1 54.1,53.4 56.55,53.4 57.725,52.225 U4.14
A4: U1.54 U4.13 | length 8.8
  Top Layer w0.3: U1.54 52.8,53.1 53.7,54 56.95,54 58.275,52.675 U4.13
A5: U1.56 U4.12 | length 11.1
  Top Layer w0.3: U1.56 51.8,53.078 53.322,54.6 57.3,54.6 58.825,53.075 U4.12
A6: U1.57 U4.11 | length 13.2
  Top Layer w0.3: U1.57 51.3,53.6 52.9,55.2 57.7,55.2 59.375,53.525 U4.11
A7: U1.58 U4.10 | length 15.4
  Top Layer w0.3: U1.58 50.8,54.1 52.5,55.8 58.2,55.8 59.925,54.075 U4.10
A8: U1.60 U4.9 | length 17.7
  Top Layer w0.3: U1.60 49.8,54.1 52.1,56.4 58.6,56.4 60.475,54.525 U4.9
A9: U1.46 U4.5 | length 9.1
  Top Layer w0.3: U1.46 61.8,48.5 62.675,49.375 U4.5
A10: U1.48 U4.8 | length 6.5
  Top Layer w0.3: U1.48 57,49.5 57.3,49.8 60.5,49.8 61.025,50.325 U4.8
ADCCLK: U1.23 U3.15 | length 11.8
  Top Layer w0.3: U1.23@53.3,37 53.3,35.993 53.593,35.7 53.6,35.7 53.7,35.6 53.7,34.2 57.075,30.825 U3.15
ADCE-: U1.25 U3.16 U3.17 | length 12.2
  Top Layer w0.3: U1.25 54.3,34.6 57.725,31.175 U3.16
  Top Layer w0.4: U3.16 U3.17
AGND: C31.1 C32.1 C33.1 C34.1 C35.1 C40.2 C41.2 C42.2 C44.2 C45.2 C46.2 C48.1 C49.A C50.A C54.C INPUT.2 LEVEL.1 Q3.2 Q4.2 Q5.2 R19.1 R20.1 R26.2 R32.2 R33.2 R34.2 U11.6 U11.8 U14.2 U14.6 U15.4 X2.5 Y.2 | length 1
  Top Layer w0.5: U14.6 v1@105.8,28.8
  other v1: 105.9,28.7 101.1,32.6
  other v2: 131.5,23.4 136.5,25.6 119.5,27.2 116.9,33.8 138.8,36.9 107.3,38.3
  other v4: 102.2,24.8
AUTO: U1.12 U2.12 | length 5.9
  Top Layer w0.3: U2.12@46.6,31.5 46.6,32.4 47.4,33.2 47.4,35.5 47.8,35.9 U1.12
AVDD: C16.1 L2.1 U3.21 U3.28 | length 13.1
  Top Layer w0.4: U3.21 60.975,29.275 61.8,30.1 63,30.1 64.6,28.5 64.9,28.5 65.525,27.875 U3.28 66.1,26.8 66.4,26.5 C16.1 67.3,28.1 L2.1
BATM: R4.1 R5.2 U2.9 | length 5.9
  Bottom Layer w0.5: v1(49.9,32.1) 50.15,31.85 50.35,31.85 R4.1@54.8,31.85 ; 53.5,31.95 R5.2
BATTERY: C26.2 P1.1 Q1.2 R6.1 U8.3 | length 14.6
  Top Layer w0.5: Q1.2 R6.1@76.15,23.15
  Top Layer w0.75: C26.2 P1.1 73.7,25.2 74.85,24.05 Q1.2
  Bottom Layer w0.75: P1.1 73.7,28.1 75.325,29.725 U8.3@78.5,29.725
COMP: U1.21 X1.4 | length 28.3
  Top Layer w0.3: U1.21 52.3,35.993 53.1,35.193 53.1,33.8 56,30.9 56,23.1 59,20.1 63.5,20.1 64.4,21 65.5,21 66.19,20.31 X1.4
D0: U1.42 U3.6 U4.25 | length 19.8
  Top Layer w0.3: U1.42 61.8,46.5 63.225,45.075 U4.25 63.225,35.825 62.275,34.875 U3.6
D1: U1.41 U3.7 U4.24 | length 18.9
  Top Layer w0.3: U1.41 57.5,46 57.7,45.8 61.5,45.8 62.675,44.625 U4.24 62.675,36.275 61.625,35.225 U3.7
D2: U1.40 U3.8 U4.23 | length 17.9
  Top Layer w0.3: U1.40 57,45.5 57.4,45.1 61.2,45.1 62.125,44.175 U4.23 62.125,36.725 60.975,35.575 U3.8
D3: U1.37 U3.9 U4.22 | length 16.8
  Top Layer w0.3: U1.37 57,44 57.5,44.5 60.7,44.5 61.575,43.625 U4.22 61.575,37.175 60.325,35.925 U3.9
D4: U1.36 U3.10 U4.20 | length 13.5
  Top Layer w0.3: U1.36 58.1,43.5 60.475,41.125 U4.20 60.475,36.975 59.675,36.175 U3.10
D5: U1.35 U3.11 U4.19 | length 12.6
  Top Layer w0.3: U1.35 57,43 57.3,42.7 58.1,42.7 59.925,40.875 U4.19 59.925,37.325 59.025,36.425 U3.11
D6: U1.32 U3.12 U4.18 | length 11.3
  Top Layer w0.3: U1.32 58.4,41.5 59.375,40.525 U4.18 59.375,37.575 58.375,36.575 U3.12
D7: U1.44 U4.26 | length 15.6
  Top Layer w0.3: U1.44 57.1,47.5 57.4,47.2 62.2,47.2 63.775,45.625 U4.26
DC0: U1.10 U2.13 | length 5.9
  Top Layer w0.3: U2.13@45.8,31.5 45.8,32.5 46.8,33.5 U1.10
DC1: U1.9 U2.14 | length 6
  Top Layer w0.3: U2.14@45,31.5 45,32.6 46.1,33.7 46.1,35.3 46.3,35.5 U1.9
DC2: U1.8 U2.15 | length 6.1
  Top Layer w0.3: U2.15@44.2,31.5 44.2,32.7 45.4,33.9 45.4,35.5 45.8,35.9 U1.8
DC3: U1.6 U2.16 | length 6
  Top Layer w0.3: U2.16 43.4,32.8 44.8,34.2 U1.6
DC4: U1.97 U2.17 | length 12.7
  Top Layer w0.3: U1.97 41.95,40 42.15,39.8 42.15,38.35 40.8,37 40.8,30.55 41.15,30.2 U2.17
DC5: U1.100 U2.18 | length 10.9
  Top Layer w0.3: U1.100 40.1,37.85 40.1,30.2 40.9,29.4 U2.18
DC6: U1.99 U2.19 | length 13.6
  Top Layer w0.3: U1.99 39.7,39 39.35,38.65 39.35,29.85 40.6,28.6 U2.19
DC7: U1.98 U2.20 | length 15.8
  Top Layer w0.3: U1.98 39.3,39.5 38.65,38.85 38.65,29.55 40.4,27.8 U2.20
DI1: R15.1 R16.1 U1.93 | length 16.5
  Top Layer w0.3: R15.1@35.8,42 U1.93
  Top Layer w0.5: R16.1 27.2,47.6 28.1,46.7 30.3,46.7 35,42 R15.1@35.8,42
DI2: R13.1 R14.1 U1.92 | length 14.6
  Top Layer w0.3: R14.1 30.7,47.4 35,43.1 36.5,43.1 37,42.6 39,42.6 39.1,42.5 U1.92
  Top Layer w0.5: R13.1 R14.1
ENDM: U1.20 U2.5 | length 13.7
  Top Layer w0.3: U2.5 53.2,27.8 54.5,29.1 54.5,31.5 52.5,33.5 52.5,35 51.8,35.7 U1.20
EXTCLK: U1.19 U2.6 | length 12.3
  Top Layer w0.3: U2.6 52.9,28.6 53.75,29.45 53.75,31.35 51.9,33.2 51.9,34.8 51.3,35.4 U1.19
F10: PA1.1 Q3.1 R32.1 | length 86.2
  Top Layer w0.5: R32.1@144.5,54.8 PA1.1
  Bottom Layer w0.5: v3@94.7,23.4 95.6,24.3 95.6,29.5 93.8,31.3 93.8,45.1 95.5,46.8 95.5,56.9 142.7,56.9 143.1,56.5 PA1.1
  other v3: 94.8,23.5
F10C: PA.1 U1.67 | length 17.3
  Top Layer w0.3: PA.1 35.2,56.5 35.8,57.1 44.9,57.1 46.3,55.7 U1.67@46.3,52
F100: PA1.2 Q4.1 R33.1 | length 87.1
  Top Layer w0.5: R33.1@145.77,54.83 PA1.2
  Bottom Layer w0.5: v3(98.4,23.8) 96.6,25.6 96.6,30 94.8,31.8 94.8,44.6 96.5,46.3 96.5,56 141.9,56 143,54.9 145.3,54.9 145.77,55.37 PA1.2
F100C: PA.2 U1.69 | length 18.7
  Top Layer w0.3: PA.2 32.23,55.57 32.6,55.2 35.5,55.2 36.8,56.5 44.6,56.5 45.3,55.8 U1.69
F1000: PA1.3 Q5.1 R34.1 | length 82.6
  Top Layer w0.5: Q5.1@98,27.4 v3(98,28.4) ; R34.1@147.04,54.96 PA1.3
  Bottom Layer w0.5: v3(98,28.4) 98,30 95.8,32.2 95.8,44.1 97.5,45.8 97.5,55.1 141.2,55.1 142.4,53.9 145.6,53.9 147.04,55.34 PA1.3
F1000C: PA.3 U1.71 | length 19.1
  Top Layer w0.3: PA.3 30.96,55.84 32.2,54.6 36.6,54.6 37.8,55.8 44.3,55.8 44.7,55.4 44.7,53.5 44.3,53.1 U1.71
GND: B1.1 B1.3 C1.1 C2.1 C3.1 C4.1 C5.1 C7.1 C9.2 C10.1 C11.1 C13.1 C15.1 C16.2 C17.2 C18.1 C19.1 C20.2 C21.1 C22.1 C23.1 C25.2 C26.1 C27.1 C28.1 JOY-A.2 JOY-A.7 JOY-A.8 JOY.2 LCD.7 LCD.10 P1.2 Q2.2 R5.1 R7.1 R10.1 R12.1 R14.2 R15.2 SWIM.3 U1.11 U1.26 U1.33 U1.38 U1.43 U1.53 U1.59 U1.65 U1.74 U1.78 U1.86 U1.95 U2.7 U3.1 U3.14 U3.19 U3.27 U4.2 U4.3 U4.4 U4.21 U4.27 U4.28 U5.4 U5.7 U6.2 U7.2 U8.2 U9.1 U9.2 USB.5 USB.6 X1.5 XDI.1 | length 62.7
  Top Layer w0: 65.525,32.675 U3.1
  Top Layer w0.3: v4@38.8,40.8 39.3,40.8 ; v4(38.8,46.9) 38.85,46.9 v4@38.9,46.85 ; 39,46 39.5,45.5 U1.86 ; 39.5,41 U1.95 ; U1.78 41.9,49.5 42.8,50.4 U1.74 ; v1(41,51.8) 42.569,50.231 ; U1.11 v1@47.3,39 ; U1.65 47.3,51 47.6,50.7 50.3,50.7 ; U1.59 50.3,50.7 ; U1.53 53.3,51 52.3,50 51,50 50.3,50.7 ; v1(53.9,47) 54.05,47 U1.43 ; v1@54,43.8 54,43.85 54.65,44.5 U1.38 ; v4@55.85,37.25 v4(55.9,37.2) ; U1.26 54.8,38.5 54.5,38.8 54.5,41.7 54.8,42 U1.33 ; v1(60.2,43.2) 60.2,43 61.025,42.175 U4.21 ; U4.4 U4.3 U4.2 ; v1(64.2,53.2) v1@64.325,53.075 ; C15.1 C15.1@64.875,37.075 ; v5@64.875,40.775 v5@64.9,40.8 ; 81.175,50.275 81.275,50.375
  Top Layer w0.4: 59.675,22.7 U3.19 ; v1@63.8,53.6 v1(64.2,53.2) ; U3.27 64.875,25.425 65.37,24.93 66.2,24.93 ; v1@66.2,24.1 66.2,24.93 ; C17.2@67.3,23.4 C16.2 ; C16.2@67.3,24.93 66.2,24.93
  Top Layer w0.45: 81.175,50.275 U5.7 81.175,46.4 81.475,46.1 81.7,46.1
  Top Layer w0.5: C13.1 59.675,22.7 v1(59.675,21.625) 60.1,21.2 C10.1 C11.1 ; C20.2@83.85,47.25 C20.2@83.9,47.2
  Bottom Layer w1.5: 67.2,30.2 v1(67.2,31.9)
  other v1: 66.5,24.2 48.4,29.2 25,30.2 47.2,39.05 23.75,43 53.8,43.8 51.8,50 78.2,55
  other v2: 70,45
  other v4: 38.7,40.7
  other v5: 65.1,40.8 82.3,45.5
J_C: D4.C D5.C JOY-A.5 JOY.5 | length 3.9
  Top Layer w0.5: JOY.5 32.3,33.2 D4.C
J_D: JOY-A.3 JOY.3 U2.30 | length 32.1
  Top Layer w0.3: 42.4,23.6 43.2,24.4 47.1,24.4 47.4,24.1 U2.30
  Top Layer w0.4: JOY.3 25.3,38.079 25.3,36.3 30.7,30.9 31.8,30.9 39.1,23.6 42.4,23.6
J_L: JOY-A.1 JOY.1 U2.22 | length 23.9
  Top Layer w0.4: JOY.1 27.321,40.3 29,40.3 34.1,35.2 34.2,35.1 34.2,31.9 39.9,26.2 U2.22
J_R: D4.A JOY-A.4 JOY.4 U2.24 | length 17.5
  Top Layer w0.5: JOY.4 31.579,31.8 32,31.8 39.2,24.6 U2.24@42.1,24.6
J_U: D5.A JOY-A.6 JOY.6 U2.23 | length 17.4
  Top Layer w0.5: JOY.6 33.2,34.421 33.2,31.8 39.6,25.4 U2.23
K1: J2.1 PA1.4 | length 65.9
  Top Layer w0.5: J2.1 125,20.9 125.3,20.6 148.9,20.6 150.5,22.2 150.5,27 149.2,28.3 149.2,46.8 152,49.6 152,52.4 151.2,53.2 150.2,53.2 148.31,55.09 PA1.4
K1C: PA.4 U1.75 | length 15.5
  Top Layer w0.3: PA.4@29.7,56.5 29.7,55.6 30.1,55.2 30.6,55.2 31.8,54 41.2,54 42.3,52.9 U1.75
K2: J3.1 PA1.5 | length 71
  Top Layer w0.5: J3.1 121.2,20.1 121.7,19.6 149.6,19.6 151.6,21.6 151.6,28.3 150.3,29.6 150.3,46.4 153.2,49.3 153.2,52.7 151.8,54.1 150.8,54.1 149.58,55.32 PA1.5
K2C: PA.5 U1.76 | length 15.4
  Top Layer w0.3: PA.5 28.42,55.58 29.5,54.5 30.3,54.5 31.4,53.4 37.1,53.4 40,50.5 U1.76
K3: J4.1 PA1.6 | length 76.9
  Top Layer w0.5: J4.1 118.9,20.2 120.5,18.6 153,18.6 155.5,21.1 155.5,51.9 152.4,55 151.4,55 150.85,55.55 PA1.6
K3C: PA.6 U1.79 | length 17.8
  Top Layer w0.3: PA.6 27.15,55.55 28.9,53.8 30,53.8 31,52.8 36.8,52.8 39.4,50.2 39.4,49.307 39.707,49 U1.79
LCLK: LCD.4 U2.31 | length 3.8
  Top Layer w0.5: LCD.4 46.81,20.51 48.2,21.9 U2.31
LCS: LCD.3 U2.29 | length 3.7
  Top Layer w0.5: LCD.3 45.54,20.54 46.6,21.6 U2.29
LDATA: LCD.5 U2.3 | length 15.1
  Top Layer w0.3: LCD.5 48.08,20.48 48.9,21.3 54,21.3 54,25.6 53.2,26.4 51.9,26.4 51.7,26.2 U2.3
LED+: C21.2 D1.C LCD.9 R9.2 | length 135.1
  Top Layer w0.4: LCD.9 53.16,19.06 52.9,18.8 41.9,18.8 41.4,19.3 41.4,20.2 31.5,30.1 29.8,30.1 26.9,33 25,33 22.3,35.7 22.3,57.8 64.1,57.8 67.1,54.8 67.1,48 67.7,47.4 76.1,47.4 77.9,49.2 C21.2 77.9,51.2 77.4,51.7 76.8,51.7 76.5,52 76.5,55.6 77.1,56.2 R9.2
LEV: C44.1 LEVEL.3 PA1.7 U14.1 | length 96.6
  Top Layer w0.5: LEVEL.3 94.4,47.6 94.4,34.4 104.9,34.4 105.4,33.9 C44.1 105.4,31.7 105.1,31.4 U14.1
  Bottom Layer w0.5: LEVEL.3 94.4,48.4 94.4,57.75 151.75,57.75 152.12,57.38 PA1.7
LEVEL: PA.7 U2.21 | length 44.1
  Top Layer w0.5: PA.7 23.1,56.5 23.1,44.7 28.1,44.7 32.4,40.4 32.4,38.6 35.2,35.8 35.2,32 40.2,27 U2.21
LRS: LCD.1 R35.1 U2.25 | length 5.3
  Top Layer w0.5: LCD.1 43,21.7 43.4,22.1 U2.25
  Bottom Layer w0.4: LCD.1 R35.1
LRST: LCD.2 R36.1 U2.26 | length 5.3
  Top Layer w0.4: LCD.2@44.2,20.07 LCD.2
  Top Layer w0.5: LCD.2@44.2,20.07 U2.26
  Bottom Layer w0.4: LCD.2 44.27,21.87 R36.1
NetB1_2: B1.2 Q1.1 Q2.3 R6.2 | length 6.6
  Top Layer w0.5: Q1.1 78.25,21.25 B1.2@78.3,21.2
  Top Layer w0.6: B1.2@78.3,21.2 78.3,22.1 79.7,23.5 Q2.3
NetC10_2: C10.2 C12.2 U3.22 | length 4.2
  Top Layer w0.4: C10.2 61.1,24.3 61.1,24.9 61.625,25.425 U3.22
NetC11_2: C11.2 C12.1 U3.24 | length 4.1
  Top Layer w0.4: C11.2 62.925,23.025 U3.24
NetC13_2: C13.2 U3.18 U3.23 | length 18.8
  Top Layer w0.4: v1(57.3,24.4) C13.2@58.4,24.4 ; C13.2 58.5,25.15 59.025,25.675 U3.18 ; U3.23 62.275,28.5 62.4,28.625 v1(62.4,28.8)
  Bottom Layer w0.4: v1(57.3,24.4) 56.75,24.95 56.75,28.625 58.625,30.5 62.4,30.5 62.4,28.7 62.4,28.625 v1@62.275,28.5
NetC19_2: C19.2 R8.1 | length 1.8
  Top Layer w0.4: C19.2@83.8,51.1 R8.1@83.8,52.9
NetC20_1: C20.1 U5.8 | length 2
  Top Layer w0.4: U5.8 81.825,47.575 C20.1
NetC25_1: C25.1 D2.A U8.4 USB.1 | length 24
  Bottom Layer w0.5: USB.1 73.7,42.5 76.9,39.3 ; U8.4 77.525,31.875 76.9,32.5 76.9,39.3 ; D2.A 76.9,39.3
  Bottom Layer w2: D2.A 82,39.3
NetC27_2: C27.2 U9.3 Y1.1 | length 3.4
  Top Layer w0.4: U9.3 C27.2@36.55,47.85
  Top Layer w0.5: Y1.1 C27.2@36.55,48
NetC28_1_1: C28_1.1 U9.4 | length 3.2
  Top Layer w0.4: C28_1.1 35,45.3 36,44.3 U9.4@36.55,44.3
NetC28_2: C28.2 C28_1.2 Y1.3 | length 9.1
  Top Layer w0.5: Y1.3 33.1,49.5 ; C28_1.2 32.6,46.5 31.9,47.2 31.9,49 32.4,49.5 33.1,49.5 ; C28.2@36.2,49.5 33.1,49.5
NetC29_1: C29.1 INPUT.1 SB1.1 SB1.3 | length 17.8
  Top Layer w0.75: INPUT.1 145.1,33.45 145.1,27.5 ; C29.1@145.1,27 145.1,27.5 ; SB1.1 149,22.5 149.4,22.9 149.4,26.3 148.2,27.5 SB1.3 145.1,27.5
NetC29_2: C29.2 C30.2 R18.2 SB1.2 | length 5.9
  Top Layer w0.75: C30.2@141.7,25.3 R18.2 C29.2 147.2,25.3 SB1.2
NetC30_1: C30.1 C31.2 D6.A D7.C R18.1 R19.2 U10.3 | length 11.5
  Top Layer w0.5: 139.15,26.95 U10.3 140.5,30.5 140.8,30.8 D6.A
  Top Layer w0.75: R19.2 C31.2 R18.1
NetC32_2: C32.2 D6.C L3.2 U10.5 U10.6 | length 9.7
  Top Layer w0.5: L3.2 137.2,35.9 137.2,34.3 ; U10.6@137.2,33.15 137.2,34.3 ; U10.5 138.2,34.3 ; D6.C 140.8,34 140.5,34.3 138.2,34.3 ; 137.2,34.3 138.2,34.3
NetC33_2: C33.2 D7.A L4.1 U10.2 | length 5
  Top Layer w0.5: L4.1 137.86,28.6 138.1,28.6 138.2,28.7 U10.2
NetC34_2: C34.2 L5.1 U11.16 | length 3.7
  Top Layer w0.5: U11.16 130.5,27.1 130.8,26.8 C34.2 133,26.8 L5.1@133.3,27.1
NetC35_2: C35.2 L6.1 U11.7 | length 4
  Top Layer w0.5: L6.1 C35.2 ; U11.7 C35.2@122.225,34.325
NetC40_1: C40.1 L9.1 U13.8 | length 5.1
  Top Layer w0.3: U13.8@114.375,30.2 U13.8
  Top Layer w0.4: L9.1@113.7,34.9 113.7,30.8 114.3,30.2 U13.8@114.375,30.2
NetC41_1: C41.1 L10.1 R28.2 U13.4 | length 5.5
  Top Layer w0.4: R28.2@115.1,24.5 116.7,24.5 ; U13.4 116.375,26.425 116.7,26.1 L10.1
NetC42_1: C42.1 C51.1 C52.1 C53.1 R40.2 X2.3 | length 11.9
  Top Layer w0.5: C53.1 C42.1 C42.1@106,24.5 ; R40.2 C42.1@106,24.5 ; X2.3@110.6,19.56 110.6,20.8 109.4,22 106,22 106,22.7 C42.1@106,24.5
NetC45_1: C45.1 L11.1 U14.4 | length 3
  Top Layer w0.5: L11.1 U14.4
NetC46_1: C46.1 X2.2 Y.3 | length 26.8
  Top Layer w0.5: Y.3 C46.1 93.2,24.8 93.2,19.5 105.7,19.5 107.2,21 108.9,21 109.27,20.63 X2.2
NetC47_1: C47.1 U15.3 | length 5.1
  Top Layer w0.5: U15.3 100.35,40.15 100.6,39.9 100.9,39.9 101.3,39.5 C47.1@101.3,36.7
NetC47_2: C47.2 U15.5 | length 2.2
  Top Layer w0.5: U15.5 102.25,38.05 102.9,37.4 C47.2@102.9,36.7
NetC48_2: C48.2 C49.C L12.1 U15.1 | length 7.9
  Top Layer w0.6: U15.1 C49.C@105.05,41.2 ; C49.C C48.2@107.35,41.25 ; C48.2 L12.1@110.25,41.3
NetC51_2: C51.2 Q3.3 | length 8.1
  Top Layer w0.5: Q3.3@97.175,21.475 98.15,20.5 102.2,20.5 103.3,21.6 C51.2
NetC52_2: C52.2 Q4.3 | length 2.6
  Top Layer w0.5: Q4.3@101.9,22.8 103.2,22.8 103.5,23.1 C52.2
NetC53_2: C53.2 Q5.3 | length 4.2
  Top Layer w0.5: Q5.3 102.7,26.4 103.1,26 C53.2
NetC54_A: C54.A L13.1 U15.2 | length 7.7
  Top Layer w0.6: L13.1@98,45.85 98,42.7 100.8,42.7 101.3,42.2 U15.2
NetD1_A: D1.A L1.2 U5.5 | length 6.8
  Top Layer w0.45: 79.3,49 U5.5
  Top Layer w0.5: D1.A 76.55,45.35 77.2,46 L1.2 78.2,47.9 79.3,49
NetD2_K: D2.K R11.1 | length 4.8
  Bottom Layer w1: 81.96,36.76 82.1,36.62 R11.1
  Bottom Layer w2: D2.K 81.96,36.76
NetD3_C: D3.C LCD.8 | length 2.4
  Bottom Layer w0.4: D3.C 51,21.7 51.89,20.81 LCD.8
NetINPUT_3: INPUT.3 XDO.3 | length 15.7
  Top Layer w0.75: INPUT.3 145.75,39.25 147.5,41 147.5,46.6 150.54,49.64 XDO.3
NetINPUT_4: INPUT.4 XDO.2 | length 11.9
  Top Layer w0.75: INPUT.4@144.3,41.7 144.3,45.1 149.27,50.07 XDO.2
NetJ1_2: J1.2 L5.2 | length 4
  Top Layer w0.5: L5.2 133.3,30.5 133.6,30.8 J1.2
NetJ2_2: J2.2 U11.11 | length 3.2
  Top Layer w0.5: J2.2 U11.11@123.5,27.095
NetJ3_2: J3.2 U11.10 | length 3.6
  Top Layer w0.5: J3.2 121.2,24.4 122.225,25.425 U11.10
NetJ4_2: J4.2 U11.9 | length 4.6
  Top Layer w0.5: J4.2 118.9,24.6 119.7,25.4 120.6,25.4 120.955,25.755 U11.9
NetJ5_1: J5.1 R29.2 U13.1 | length 3.4
  Top Layer w0.4: J5.1 112.4,28.9 113.1,28.2 R29.2 ; R29.2@113.1,27.45 U13.1
NetJ5_2: J5.2 R30.1 R40.1 | length 7
  Top Layer w0.5: J5.2 R30.1@109.4,31.35 ; R40.1 J5.2@109.45,29.4
NetR8_2: R8.2 U5.1 | length 2.7
  Top Layer w0.4: U5.1 81.825,53.925 82.4,54.5 R8.2@83.8,54.5
NetR9_1: R9.1 R10.2 U5.2 | length 5.4
  Top Layer w0.4: R9.1 80.2,56.9 81.175,55.925
  Top Layer w0.45: U5.2 81.175,55.925
NetR11_2: R11.2 U8.1 | length 4.3
  Bottom Layer w0.5: U8.1 81.025,29.725 82.1,30.8 R11.2@82.1,33.1
NetR12_2: R12.2 U8.5 | length 2.1
  Bottom Layer w0.5: U8.5 R12.2@80.55,33.95
NetR13_2: R13.2 XDI.2 | length 1.8
  Top Layer w0.75: XDI.2 28.73,50.07 R13.2
NetR16_2: R16.2 XDI.3 | length 1.6
  Top Layer w0.75: R16.2@27.2,50 27.2,50.5 27.46,50.76 XDI.3
NetR20_2: R20.2 R21.1 U11.13 | length 6.1
  Top Layer w0.5: U11.13 126.035,26.235 125.2,25.4 R21.1 125.2,24.1 126.4,22.9 R20.2
NetR21_2: R21.2 R22.1 U11.14 | length 3.4
  Top Layer w0.5: U11.14 127.305,24.905 127.3,24.9 127.8,24.9 R22.1
NetR22_2: R22.2 R23.1 U11.15 | length 7.9
  Top Layer w0.5: R22.2 129.9,24.9 128.6,26.2 128.6,28.3 129.1,28.8 130.4,28.8 130.8,28.4 R23.1
NetR23_2: R23.2 R24.1 U11.12 | length 10.8
  Top Layer w0.5: U11.12 124.765,28.665 125.3,29.2 127.7,29.2 128.5,30 R23.2 R24.1
NetR24_2: R24.2 R25.1 U11.1 | length 5.4
  Top Layer w0.5: R25.1 128.5,34.3 129.555,33.245 R24.2@131.645,33.245 ; U11.1 129.845,33.19
NetR25_2: R25.2 U10.1 U10.4 U11.5 | length 21.1
  Top Layer w0.5: U11.5 124.765,33.265 125.8,34.3 R25.2 126.4,35.2 126.7,35.5 131.3,35.5 132.8,34 134.5,34 136.7,31.8 137.25,31.8 ; U10.1 137.25,31.8 ; U10.4 139.15,32.15 138.8,31.8 137.25,31.8
NetR26_1: R26.1 R27.1 U13.6 | length 5.1
  Top Layer w0.4: R27.1 116.7,31.7 115.725,30.725 U13.6 115.725,29.375 116,29.1 R26.1
NetR27_2: R27.2 U13.3 U13.7 | length 4.6
  Top Layer w0.4: R27.2@115.075,31.8 U13.7 115.075,28.925 115.725,28.275 U13.3
NetR28_1: R28.1 R29.1 U13.2 | length 3.3
  Top Layer w0.4: R28.1@115.075,26.125 U13.2
  Top Layer w0.5: R29.1 R28.1
NetR30_2: R30.2 R41.1 U14.3 | length 8.5
  Top Layer w0.5: U14.3 102.85,30.35 103.1,30.1 107.8,30.1 ; R41.1@107.8,29 R30.2
NetR41_2: R41.2 U14.5 X2.4 | length 15.6
  Top Layer w0.3: R41.2 108.5,26.6 108.5,23
  Top Layer w0.5: U14.5 103.8,27.8 104.3,27.3 R41.2 ; 108.5,23 110.1,23 111.81,21.29 X2.4
NetR45_1: R45.1 U3.26 X1.2 | length 17.5
  Top Layer w0.4: R45.1 63.1,18.9 63.7,18.3 68.5,18.3 68.73,18.53 X1.2 68.73,20.57 67,22.3 66.4,22.3 64.225,24.475 U3.26
NetU1_17: U1.17 U2.2 | length 18
  Top Layer w0.3: U1.17 50.3,35.5 51.2,34.6 51.2,31.3 50.75,30.85 49.584,30.85 49.259,30.525 47.225,30.525 46.9,30.2 46.9,27.1 48.6,25.4 U2.2
NetU1_87: U1.87 U9.6 | length 3.2
  Top Layer w0.3: U9.6@37.85,44.3 38.8,44.3 39.5,45 U1.87
NetU3_25: U3.25 X1.3 | length 9.2
  Top Layer w0.4: U3.25 63.575,24.025 66.1,21.5 66.6,21.5 67.46,20.64 X1.3
NetU11_3: U11.3 U13.5 | length 13.3
  Top Layer w0.4: U13.5 118.994,30.15 120.044,29.1 123.6,29.1 124.65,30.15 126.85,30.15 127.305,30.605 U11.3
OE-: U1.45 U4.1 | length 11.1
  Top Layer w0.3: U1.45 57.563,48 57.663,47.9 62.6,47.9 64.875,50.175 U4.1
PWR_ON: Q2.1 R7.2 U2.4 | length 44.2
  Top Layer w0.3: U2.4 53.6,27 54.8,25.8 54.8,22.4 56.75,20.45 v3@56.75,19.05
  Top Layer w0.5: R7.2 80.6,25.1 81.2,24.5 v1(81.2,23.4)
  Bottom Layer w0.4: v3(56.8,19) 57.5,18.3 73.9,18.3
  Bottom Layer w0.5: 73.9,18.3 79,23.4 v1(81.2,23.4)
RESET: C5.2 SWIM.2 U2.1 | length 4.1
  Top Layer w0.5: U2.1 51.9,24.6 SWIM.2@52.45,25.15
  Bottom Layer w0.5: SWIM.2 52.86,25.55 C5.2
START: U1.13 U2.11 | length 5.8
  Top Layer w0.3: U2.11@47.4,31.5 47.4,32.3 48,32.9 48,35.3 48.3,35.6 U1.13
SWIM: SWIM.1 U2.32 | length 3.7
  Top Layer w0.5: U2.32 49.85,23.25 50.5,22.6 SWIM.1
TCK: TCK.1 U1.62 | length 3.5
  Top Layer w0.3: U1.62 TCK.1
TDI: TDI.1 U1.4 | length 2.7
  Top Layer w0.3: TDI.1@43,34.6 43.8,35.4 U1.4
TDO: TDO.1 U1.73 | length 2.2
  Top Layer w0.3: U1.73 TDO.1@43.3,54.3
TMS: TMS.1 U1.15 | length 3.1
  Top Layer w0.3: U1.15 49.3,35.6 49.9,35 TMS.1
URX: R45.2 U2.27 | length 3.2
  Top Layer w0.5: 45,21.7 U2.27
  Top Layer w0.75: 58.8,18.9 R45.2
UTX: U2.28 | length 1.1
  Top Layer w0.5: 45.8,22.1 U2.28
VBAT: C18.2 L1.1 Q1.3 R4.2 U5.3 U5.6 U6.1 U6.3 U7.1 U7.3 | length 64.7
  Top Layer w0.4: U5.6@80.525,48.95 U5.6
  Top Layer w0.45: 79.8,47.2 80.525,47.925 U5.6 U5.3
  Top Layer w0.5: U6.3 v1@67.85,38 ; U7.1 v1(67.85,38.3) v1@67.85,38 ; U6.1 69.75,38 ; U7.3 69.75,38 ; 71.6,38 71.6,23.15 Q1.3 ; 79.8,43.7 C18.2 ; 79.8,47.2 L1.1 79.8,43.5 74.3,38 69.75,38 ; v1@67.85,38 69.75,38
  Bottom Layer w0.5: R4.2@56.5,31.85 57.3,31.85 57.7,32.25 61.5,32.25 64.8,35.55 64.8,36.85 66.25,38.3 v1(67.85,38.3)
WE-: U1.47 U4.6 | length 8
  Top Layer w0.3: U1.47 57.6,49 57.8,49.2 61.35,49.2 62.125,49.975 U4.6
WR0: U1.14 U2.10 | length 5.6
  Top Layer w0.3: U2.10 48.2,32.2 48.6,32.6 48.6,35 48.8,35.2 U1.14
pads on no net: B1.4 INPUT.5 JOY.7 JOY.8 SB1.4 SB1.5 SB1.6 U1.1 U1.2 U1.5 U1.7 U1.16 U1.22 U1.24 U1.27 U1.28 U1.49 U1.50 U1.55 U1.61 U1.63 U1.64 U1.68 U1.70 U1.72 U1.77 U1.80 U1.81 U1.83 U1.84 U1.85 U1.88 U1.89 U1.90 U1.94 U1.96 U3.3 U3.4 U3.5 U3.13 U3.20 U6.4 U7.4 U11.2 U11.4 USB.2 USB.3 USB.4 XDO.1 Y1.2 Y1.4

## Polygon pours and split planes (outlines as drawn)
GND on Top Layer "Out Board-No Net" (solid, remove dead copper, pour order 8): 22,58 68.2,58 68.2,51.1 67.8,51.1 67.8,48.6 76.4,48.6 76.4,51.1 76,51.1 76,58 87.5,58 87.5,18 39,18 39,19 22,19
AGND on Top Layer "Out Board-No Net" (solid, remove dead copper, pour order 5): 90.5,18 90.5,58 156,58 156,18
+3V on Top Layer "Out Board-No Net" (solid, remove dead copper, pour order 9): 54.5,50.5 42,50.5 42,38.5 54.5,38.5
GND on Bottom Layer "Out Board-No Net" (solid, remove dead copper, pour order 6): 22,58 87.5,58 87.5,18 39,18 39,19 22,19
AGND on Bottom Layer "Out Board-No Net" (solid, remove dead copper, pour order 7): 90.5,18 90.5,58 156,58 156,18

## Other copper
Top Layer:
  pour cut-out: 77,48 77,44 81,44 81,48
  pour cut-out: 56,18 56,31 66,31 66.5,30.5 71,30.5 71,18
  pour cut-out: 35.9,45.8 36.9,45.8 36.9,44.7 35.9,44.7
  pour cut-out: 140.3,33 140.3,31.9 141.3,31.9 141.3,33
Bottom Layer:
  pour cut-out: 83.5,32 85,32 85,23.8 83.5,23.8
  pour cut-out: 83.4,44 83.4,52.4 85,52.4 85,44
  pour cut-out: 66.2,58 66.2,48.5 69,48.5 69,47.8 65.5,47.8 65.5,58
  pour cut-out: 68.2,58 68.2,51.1 67.8,51.1 67.8,48.6 76.4,48.6 76.4,51.1 76,51.1 76,58
  pour cut-out: 57,18 57,29 58.5,30.5 70.5,30.5 70.5,18.6 71.5,18.6 71.5,31.3 58.2,31.3 56.2,29.3 56.2,18

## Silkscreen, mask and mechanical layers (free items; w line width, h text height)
Out Board:
  lines w0.1: 22,19 22,58 68.2,58 68.2,51.1 67.8,51.1 67.8,48.6 76.4,48.6 76.4,51.1 76,51.1 76,58 87.5,58 87.5,18 39,18 39,19 22,19 ; 90.5,18 156,18 156,58 90.5,58 90.5,18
